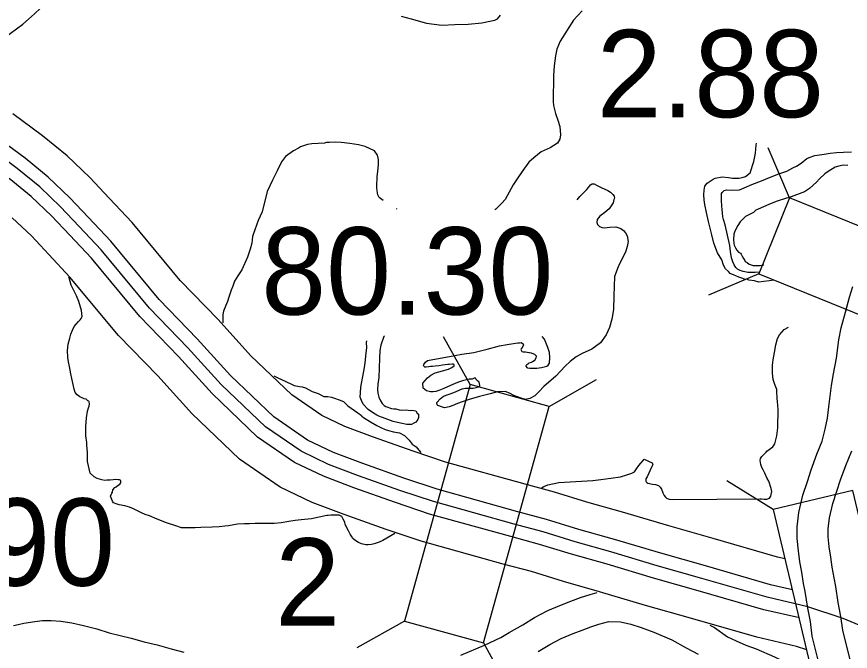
# Model space of a CAD drawing. Extents: x -83719 to 153526, y -11835 to 11446.
# Drawn here: x -2121.1 to -1986.7, y 1350 to 1452.3 of the extents above; entities that cross this region are included whole.
import ezdxf

# ---------------------------------------------------------------- set-up
doc = ezdxf.new("R2010")
doc.units = 0
for name, color, linetype in [('Level 10', 7, 'Continuous'), ('Level 19', 7, 'Continuous'), ('Level 20', 7, 'Continuous'), ('Level 23', 7, 'Continuous'), ('Level 25', 7, 'Continuous'), ('Level 58', 7, 'Continuous'), ('Level 59', 7, 'Continuous'), ('Level 9', 7, 'Continuous')]:
    doc.layers.add(name, color=color, linetype=linetype)

msp = doc.modelspace()

# ---------------------------------------------------------------- linework, layer by layer
at = {"layer": 'Level 10'}
for points in [[(-1991.5, 1347.1), (-1992.84, 1352.48), (-1993.16, 1354.81), (-1993.59, 1356.99), (-1994, 1359.64), (-1994.25, 1360.97), (-1994.55, 1362.76), (-1994.83, 1364.44), (-1995.07, 1366.21), (-1995.3, 1368.2), (-1995.29, 1370.09), (-1995.02, 1372.4), (-1994.38, 1375.18), (-1993.64, 1377.42), (-1993.01, 1379.3), (-1992.09, 1381.82), (-1991.23, 1383.88), (-1990.76, 1385.81), (-1990.41, 1387.58), (-1990.17, 1389.45), (-1989.74, 1392.87), (-1989.41, 1394.76), (-1988.94, 1397.26), (-1988.56, 1400.24), (-1988.19, 1402.19), (-1987.5, 1404.7), (-1986.83, 1407.14), (-1986.31, 1408.86)], [(-2049.5, 1349.39), (-2045.71, 1351.01), (-2043.08, 1352.24), (-2041.75, 1353.07), (-2039.54, 1354.29), (-2037.62, 1355.45), (-2035.48, 1356.58), (-2033.31, 1357.49), (-2031.76, 1358.1), (-2030.24, 1358.69), (-2028.65, 1359.19), (-2027.54, 1359.49)], [(-2121.67, 1354.19), (-2120.91, 1354.34), (-2120.01, 1354.54), (-2118.19, 1354.84), (-2116.98, 1354.96), (-2115.6, 1354.98), (-2114.02, 1354.87), (-2112.25, 1354.61), (-2110.34, 1354.18), (-2108.21, 1353.64), (-2106.25, 1352.98), (-2104.43, 1352.54), (-2102.67, 1352.11), (-2100.6, 1351.55), (-2098.5, 1351.05), (-2096.22, 1350.43), (-2094.2, 1349.89)], [(-2009.39, 1354.23), (-2008.63, 1353.83), (-2006.52, 1352.35), (-2005.1, 1351.68), (-2003.54, 1350.98), (-2001.87, 1350.44), (-1998.96, 1349.11), (-1997.59, 1348.47), (-1995.39, 1347.55), (-1994.06, 1347.05), (-1993.33, 1346.84), (-1992.24, 1346.72), (-1991.76, 1346.68)]]:
    msp.add_lwpolyline(points, dxfattribs=at)
at = {"layer": 'Level 19'}
for points in [[(-1997.23, 1364.91), (-1998.45, 1365.19), (-2008.83, 1368.18), (-2015.99, 1370.22), (-2023.46, 1372.44), (-2029.21, 1374.07), (-2034.4, 1375.67), (-2039.14, 1376.95), (-2051.99, 1380.52), (-2057.2, 1382.26), (-2063.74, 1384.58), (-2068.23, 1386.28), (-2071.94, 1388.06), (-2076.79, 1391.38), (-2083.36, 1397.66), (-2088.67, 1403.52), (-2094.77, 1409.83), (-2102.54, 1419.16), (-2106.2, 1423.1), (-2109.32, 1426.4), (-2113.02, 1429.91), (-2116.98, 1433.15), (-2121.78, 1436.68)], [(-1996.06, 1359.93), (-1999.6, 1360.76), (-2010.09, 1363.77), (-2017.27, 1365.82), (-2024.73, 1368.04), (-2030.51, 1369.68), (-2035.68, 1371.26), (-2040.35, 1372.53), (-2053.33, 1376.14), (-2058.69, 1377.93), (-2065.31, 1380.28), (-2070.03, 1382.06), (-2074.24, 1384.08), (-2079.69, 1387.81), (-2086.65, 1394.46), (-2092.01, 1400.39), (-2098.18, 1406.76), (-2105.98, 1416.13), (-2109.55, 1419.96), (-2112.57, 1423.16), (-2116.05, 1426.47), (-2119.79, 1429.53), (-2124.28, 1432.83)], [(-1994.92, 1355.39), (-2000.65, 1356.72), (-2011.24, 1359.77), (-2018.44, 1361.82), (-2025.9, 1364.04), (-2031.69, 1365.68), (-2036.83, 1367.26), (-2041.45, 1368.51), (-2054.55, 1372.15), (-2060.05, 1373.99), (-2066.75, 1376.36), (-2071.68, 1378.23), (-2076.33, 1380.47), (-2082.32, 1384.56), (-2089.64, 1391.56), (-2095.05, 1397.54), (-2101.28, 1403.98), (-2109.1, 1413.38), (-2112.58, 1417.11), (-2115.52, 1420.22), (-2118.81, 1423.34), (-2122.35, 1426.23)], [(-1993.71, 1350.23), (-1995.37, 1350.79), (-2001.81, 1352.28), (-2012.5, 1355.36), (-2019.72, 1357.42), (-2027.17, 1359.63), (-2032.99, 1361.28), (-2038.11, 1362.86), (-2042.67, 1364.09), (-2055.9, 1367.77), (-2061.54, 1369.66), (-2068.32, 1372.06), (-2073.48, 1374.01), (-2078.63, 1376.49), (-2085.22, 1380.99), (-2092.92, 1388.36), (-2098.4, 1394.41), (-2104.7, 1400.91), (-2112.55, 1410.34), (-2115.93, 1413.97), (-2118.77, 1416.98), (-2121.84, 1419.9)]]:
    msp.add_lwpolyline(points, dxfattribs=at)
at = {"layer": 'Level 20'}
for p, q in [((-1996.52, 1423.12), (-1999.95, 1431.22)), ((-2001.48, 1410.89), (-2009.58, 1407.46)), ((-2048.01, 1393.05), (-2052.33, 1400.71)), ((-2035.29, 1389.51), (-2027.63, 1393.84)), ((-1999.15, 1372.9), (-2006.65, 1377.52)), ((-2058.61, 1354.89), (-2066.27, 1350.56)), ((-2045.89, 1351.36), (-2041.56, 1343.7))]:
    msp.add_line(p, q, dxfattribs=at)
for points in [[(-2001.48, 1410.89), (-1964.78, 1396.01), (-1959.82, 1408.24), (-1996.52, 1423.12)], [(-2048.01, 1393.05), (-2058.61, 1354.89), (-2045.89, 1351.36), (-2035.29, 1389.51)], [(-1999.15, 1372.9), (-1990.01, 1334.37), (-1977.17, 1337.42), (-1986.31, 1375.95)]]:
    msp.add_lwpolyline(points, close=True, dxfattribs=at)
at = {"layer": 'Level 23'}
msp.add_arc((-2145.6, 1482.39), 40.29, 296.5429, 353.6077, dxfattribs=at)
at = {"layer": 'Level 59'}
for points in [[(-1983.1, 1353.34), (-1987.89, 1355.3), (-1993.55, 1357.21), (-2000.13, 1358.74), (-2010.66, 1361.77), (-2017.86, 1363.82), (-2025.32, 1366.04), (-2031.1, 1367.68), (-2036.25, 1369.26), (-2040.9, 1370.52), (-2053.94, 1374.15), (-2059.37, 1375.96), (-2066.03, 1378.32), (-2070.85, 1380.14), (-2075.28, 1382.27), (-2081.01, 1386.19), (-2088.14, 1393.01), (-2093.53, 1398.96), (-2099.73, 1405.37), (-2107.54, 1414.75), (-2111.07, 1418.53), (-2114.05, 1421.69), (-2117.43, 1424.9), (-2121.07, 1427.88), (-2125.42, 1431.08)], [(-1986.68, 1348.41), (-1987.92, 1353.43), (-1988.23, 1355.63), (-1988.66, 1357.86), (-1989.07, 1360.49), (-1989.33, 1361.85), (-1989.62, 1363.58), (-1989.88, 1365.18), (-1990.11, 1366.84), (-1990.3, 1368.48), (-1990.29, 1369.78), (-1990.09, 1371.55), (-1989.56, 1373.83), (-1988.89, 1375.84), (-1988.29, 1377.65), (-1987.43, 1380), (-1986.47, 1382.32)], [(-2037.04, 1349.96), (-2035.16, 1351.09), (-2033.34, 1352.06), (-2031.42, 1352.86), (-2029.94, 1353.45), (-2028.58, 1353.97), (-2027.26, 1354.39), (-2025.63, 1354.82), (-2023.77, 1354.75), (-2022.13, 1354.41), (-2020.46, 1353.87), (-2018.41, 1353.1), (-2015.5, 1351.85), (-2013.21, 1350.58), (-2011.23, 1349.55)]]:
    msp.add_lwpolyline(points, dxfattribs=at)
at = {"layer": 'Level 9'}
for points in [[(-2029.97, 1453.26), (-2031.35, 1451.8), (-2033.52, 1448.4), (-2034.03, 1447.09), (-2034.25, 1446.05), (-2034.49, 1444.44), (-2034.56, 1442.84), (-2034.63, 1438.67), (-2034.55, 1438), (-2034.23, 1436.74), (-2033.88, 1435.68), (-2033.56, 1434.61), (-2033.47, 1433.31), (-2033.56, 1432.58), (-2033.92, 1431.97), (-2035.11, 1431.22), (-2036.56, 1430.53), (-2037.77, 1429.57), (-2038.53, 1428.89), (-2039.54, 1427.54), (-2040.45, 1426.19), (-2041.1, 1425.25), (-2042.39, 1422.86), (-2042.91, 1422.25), (-2043.9, 1421.33), (-2044.03, 1421.22)], [(-2059.12, 1452.45), (-2057.55, 1452.01), (-2055.08, 1451.32), (-2052.57, 1450.96), (-2050.48, 1451.06), (-2048.35, 1451.16), (-2046.12, 1451.33), (-2044.83, 1451.62), (-2044.03, 1451.8), (-2043.6, 1452), (-2043.14, 1452.58)], [(-2062.04, 1422.71), (-2062.67, 1423.19), (-2062.91, 1423.62), (-2062.99, 1424.26), (-2063.06, 1424.79), (-2063.08, 1425.52), (-2063.02, 1426.06), (-2062.99, 1426.53), (-2062.91, 1427.43), (-2062.79, 1428.43), (-2062.77, 1429.33), (-2062.95, 1430.03), (-2063.46, 1430.69), (-2064.97, 1431.4), (-2066.01, 1431.68), (-2067.44, 1431.89), (-2068.81, 1432.04), (-2069.71, 1432.09), (-2070.67, 1432.07), (-2071.17, 1432.03), (-2071.5, 1431.96), (-2073.57, 1431.86), (-2074.23, 1431.71), (-2075.39, 1431.33), (-2075.72, 1431.16), (-2076.48, 1430.71), (-2077.79, 1429.79), (-2078.44, 1428.94), (-2079.12, 1427.5), (-2079.89, 1425.98), (-2080.73, 1424.17), (-2081.57, 1420.85), (-2082.19, 1419.5), (-2082.73, 1417.96), (-2083.11, 1416.89), (-2083.22, 1415.82), (-2083.47, 1414.88), (-2083.92, 1413.54), (-2084.85, 1411.52), (-2085.5, 1410.54), (-2085.99, 1409.7), (-2086.31, 1408.89), (-2086.53, 1408.25), (-2086.91, 1407.11), (-2087.16, 1406.41), (-2087.48, 1405.64), (-2087.8, 1404.86), (-2087.9, 1404.33), (-2087.92, 1404.03), (-2087.91, 1403.33), (-2087.87, 1402.98)], [(-2009.04, 1417.16), (-2009.58, 1419.32), (-2009.9, 1420.75), (-2010.19, 1422.08), (-2010.27, 1422.81), (-2010.31, 1423.61), (-2010.29, 1424.38), (-2010.2, 1425.02), (-2009.78, 1425.52), (-2009.32, 1425.83), (-2008.82, 1426.17), (-2008.53, 1426.28), (-2007.4, 1426.5), (-2006.36, 1426.41), (-2005.73, 1426.32), (-2005.13, 1426.3), (-2004.66, 1426.31), (-2004.17, 1426.42), (-2003.64, 1426.56), (-2002.85, 1427.17), (-2002.28, 1428.98), (-2002.03, 1430.36), (-2001.89, 1431.63), (-2001.83, 1431.94)], [(-2006.66, 1424.41), (-2005.73, 1424.35), (-2004.57, 1424.41), (-2003.81, 1424.72), (-2002.58, 1425.31), (-2001.06, 1425.9), (-1999.74, 1426.39), (-1998.25, 1427.01), (-1996.96, 1427.43), (-1996, 1427.95), (-1995.37, 1428.26), (-1994.65, 1428.71), (-1993.7, 1429.49), (-1993.33, 1429.66), (-1992.44, 1429.98), (-1990.95, 1430.17), (-1989.95, 1430.32), (-1988.95, 1430.43), (-1987.79, 1430.52), (-1986.52, 1430.57)], [(-1987.12, 1428.35), (-1987.89, 1428.42), (-1988.58, 1428.24), (-1989.15, 1428.06), (-1990.27, 1427.38), (-1990.83, 1427), (-1991.68, 1426.19), (-1992.17, 1425.64), (-1993.29, 1424.66), (-1994.11, 1424.11), (-1996.26, 1423.31), (-1997.15, 1423.03), (-1998.51, 1422.57), (-1999.74, 1422.12), (-2000.36, 1421.87), (-2001.95, 1421.15), (-2002.34, 1420.77), (-2003.63, 1420.12), (-2003.96, 1419.78), (-2004.45, 1419.27), (-2004.84, 1418.66), (-2005.36, 1417.75), (-2005.48, 1417.28), (-2005.53, 1416.38), (-2005.52, 1415.82), (-2005.45, 1415.52), (-2005.25, 1415.05), (-2005.04, 1414.72), (-2004.77, 1414.36), (-2004.53, 1414.26), (-2004.43, 1414.2), (-2004.3, 1414.03), (-2004.16, 1413.74), (-2003.95, 1413.37), (-2003.71, 1413.01), (-2003.65, 1412.88), (-2003.34, 1412.68), (-2003.04, 1412.42), (-2002.84, 1412.36), (-2002.37, 1412.2), (-2001.67, 1412.21), (-2001.24, 1412.21), (-2000.65, 1412.34)], [(-2030.75, 1422.81), (-2030.32, 1423.35), (-2029.53, 1424.13), (-2029.2, 1424.47), (-2028.94, 1424.81), (-2028.62, 1425.25), (-2028.35, 1425.39), (-2028.02, 1425.39), (-2027.65, 1425.2), (-2026.88, 1424.81), (-2025.84, 1424.29), (-2025.4, 1424.03), (-2024.99, 1423.67), (-2024.79, 1423.38), (-2024.75, 1423.08), (-2024.85, 1422.84), (-2024.97, 1422.34), (-2025.62, 1421.36), (-2026.31, 1420.78), (-2027.1, 1420.17), (-2027.56, 1419.63), (-2027.58, 1419.13), (-2027.48, 1418.86), (-2027.17, 1418.53), (-2026.74, 1418.37), (-2026.37, 1418.31), (-2025.47, 1418.43), (-2024.54, 1418.44), (-2023.74, 1418.19), (-2023.3, 1417.86), (-2022.96, 1417.47), (-2022.72, 1417), (-2022.51, 1416.07), (-2022.69, 1415.27), (-2022.98, 1414.36), (-2023.59, 1413.15), (-2024.17, 1412.01), (-2024.74, 1410.43), (-2024.82, 1408.86), (-2024.86, 1407.32), (-2024.89, 1405.15), (-2025.16, 1403.55), (-2025.54, 1402.24), (-2026.09, 1401.03), (-2027, 1399.78), (-2028.41, 1398.72), (-2029.93, 1398.06), (-2030.92, 1397.48), (-2031.88, 1396.73), (-2032.7, 1395.98), (-2034.2, 1394.39), (-2036.14, 1392.72), (-2036.92, 1391.84), (-2037.58, 1391.23), (-2038.37, 1390.79), (-2039.07, 1390.61), (-2039.8, 1390.83), (-2040.98, 1391.28), (-2041.65, 1391.63), (-2042.35, 1391.89), (-2043.62, 1391.87), (-2044.77, 1391.52), (-2046.53, 1391.09), (-2048.16, 1390.59), (-2049.45, 1390.17), (-2050.31, 1389.86), (-2050.67, 1389.72), (-2051.4, 1389.41), (-2052.16, 1389.29), (-2052.66, 1389.45), (-2053.07, 1389.61), (-2053.23, 1389.64), (-2053.33, 1389.74), (-2053.41, 1390.14), (-2052.85, 1390.72), (-2052.29, 1391.13), (-2050.67, 1391.72), (-2049.28, 1392.31), (-2048.75, 1392.42), (-2048.12, 1392.43), (-2047.52, 1392.44), (-2047.06, 1392.55)], [(-2001.33, 1411.14), (-2002.05, 1411.1), (-2002.68, 1411.09), (-2003.22, 1411.11), (-2003.48, 1411.14), (-2003.99, 1411.27), (-2004.45, 1411.43), (-2004.89, 1411.62), (-2005.19, 1411.88), (-2005.47, 1412.31), (-2005.64, 1412.81), (-2005.89, 1413.47), (-2006.03, 1414.47), (-2006.15, 1415.44), (-2006.87, 1418.8), (-2007.15, 1419.63), (-2007.26, 1420.09), (-2007.3, 1420.69), (-2007.38, 1421.22), (-2007.42, 1421.82), (-2007.47, 1422.72), (-2007.48, 1423.23), (-2007.51, 1423.46), (-2007.49, 1423.83), (-2007.39, 1423.99), (-2007.29, 1424.1), (-2007.06, 1424.3), (-2006.66, 1424.41)], [(-2059.81, 1421.3), (-2059.91, 1421.36)], [(-1999.05, 1409.87), (-1999.73, 1409.77), (-2000.66, 1409.62), (-2001.49, 1409.54), (-2002.16, 1409.76), (-2003.06, 1409.88), (-2003.3, 1409.94), (-2003.8, 1410.04), (-2004.2, 1410.16), (-2004.7, 1410.36), (-2005.17, 1410.55), (-2005.44, 1410.64), (-2006.08, 1410.93), (-2006.38, 1411.23), (-2006.82, 1411.66), (-2007.16, 1412.28), (-2007.44, 1413.11), (-2008.13, 1414.27), (-2008.72, 1415.8), (-2009.04, 1417.16)], [(-2073.61, 1371.39), (-2075.24, 1371.23), (-2076.23, 1371.11), (-2077.26, 1370.93), (-2078.49, 1370.71), (-2079.62, 1370.62), (-2081.38, 1370.6), (-2082.68, 1370.61), (-2083.61, 1370.59), (-2084.38, 1370.58), (-2085.54, 1370.49), (-2086.97, 1370.24), (-2087.57, 1370.19), (-2088.5, 1370.11), (-2089.63, 1370.03), (-2091.43, 1370), (-2092.36, 1369.92), (-2093.56, 1369.9), (-2094.56, 1369.95), (-2095.46, 1370.27), (-2097, 1370.71), (-2098.51, 1371.32), (-2099.71, 1371.87), (-2100.42, 1372.05), (-2101.02, 1372.34), (-2102.3, 1372.99), (-2102.93, 1373.28), (-2103.7, 1373.47), (-2104.6, 1373.65), (-2104.94, 1373.75), (-2105.51, 1373.97), (-2105.71, 1374.2), (-2105.99, 1375.03), (-2105.8, 1375.54), (-2105.7, 1375.67), (-2105.61, 1376.04), (-2105.32, 1376.41), (-2105.08, 1376.55), (-2104.79, 1376.79), (-2104.49, 1376.99), (-2104.36, 1377.16), (-2104.36, 1377.33), (-2104.33, 1377.53), (-2104.57, 1377.66), (-2104.8, 1377.69), (-2105.17, 1377.72), (-2105.6, 1377.68), (-2106.07, 1377.6), (-2106.6, 1377.59), (-2106.93, 1377.55), (-2107.4, 1377.65), (-2108.17, 1377.87), (-2108.67, 1378.16), (-2109.28, 1378.72), (-2109.71, 1380.61), (-2109.72, 1381.28), (-2109.74, 1382.05), (-2109.85, 1383.25), (-2109.83, 1383.71), (-2109.98, 1384.78), (-2109.97, 1386.28), (-2109.92, 1386.95), (-2109.86, 1387.68), (-2109.71, 1388.72), (-2109.55, 1389.29), (-2109.46, 1389.53), (-2109.4, 1389.93), (-2109.44, 1390.23), (-2109.5, 1390.33), (-2109.64, 1390.42), (-2109.91, 1390.65), (-2110.24, 1390.72), (-2110.48, 1390.81), (-2110.95, 1391.07), (-2111.39, 1391.36), (-2111.69, 1391.73), (-2111.87, 1392.26), (-2112.01, 1393.02), (-2112.23, 1393.99), (-2112.41, 1394.78), (-2112.63, 1395.95), (-2112.77, 1396.68), (-2112.88, 1397.41), (-2112.97, 1398.51), (-2112.85, 1399.52), (-2112.57, 1400.52), (-2112.41, 1401.16), (-2112.16, 1401.8), (-2111.87, 1402.37), (-2111.54, 1402.77), (-2111.15, 1403.18), (-2110.88, 1403.45), (-2110.72, 1403.69), (-2110.59, 1404.02), (-2110.68, 1404.99), (-2111.1, 1406.42), (-2111.48, 1407.31), (-2112.37, 1409.07), (-2112.69, 1410.23), (-2112.71, 1410.32)], [(-2036.54, 1376.34), (-2036.14, 1376.57), (-2035.48, 1376.88), (-2033.72, 1377.21), (-2028.23, 1377.54), (-2026.97, 1377.72), (-2025.34, 1377.92), (-2023.78, 1378.14), (-2022.76, 1378.49), (-2021.96, 1378.74), (-2021.53, 1378.98), (-2021.17, 1379.42), (-2020.82, 1379.96), (-2020.49, 1380.36), (-2020.13, 1380.8), (-2019.97, 1380.97), (-2018.66, 1380.39), (-2018.56, 1380.16), (-2018.72, 1379.79), (-2019.49, 1378.15), (-2019.68, 1377.84), (-2019.71, 1377.47), (-2019.64, 1377.34), (-2019.51, 1377.24), (-2019.34, 1377.15), (-2018.6, 1376.99), (-2018.14, 1376.9), (-2017.67, 1376.74), (-2017.36, 1376.48), (-2017.16, 1376.15), (-2016.95, 1375.58), (-2016.74, 1375.15), (-2016.54, 1374.89), (-2016.34, 1374.69), (-2015.9, 1374.53), (-2015.17, 1374.51), (-2001.29, 1374.6), (-2001.02, 1374.58), (-2000.62, 1374.52), (-2000.19, 1374.52), (-1999.76, 1374.7), (-1999.53, 1375.03), (-1999.47, 1375.3), (-1999.38, 1375.77), (-1999.48, 1376.27), (-1999.87, 1377.46), (-2000.11, 1377.89), (-2000.52, 1378.72), (-2000.76, 1379.28), (-2000.97, 1379.65), (-2001.14, 1380.11), (-2001.26, 1380.78), (-2001.19, 1381.08), (-2000.97, 1381.45), (-2000.64, 1381.76), (-2000.28, 1382.13), (-2000.15, 1382.26), (-1999.19, 1383.01), (-1998.9, 1383.45), (-1998.56, 1384.76), (-1998.38, 1386.03), (-1998.36, 1389), (-1998.48, 1390.3), (-1998.49, 1390.8), (-1998.54, 1391.97), (-1998.58, 1392.23), (-1998.86, 1393.03), (-1999.03, 1393.5), (-1999.14, 1393.86), (-1999.26, 1394.86), (-1999.24, 1396.13), (-1999.16, 1397), (-1998.94, 1398.2), (-1998.7, 1399.44), (-1998.45, 1400.45), (-1998.16, 1401.05), (-1997.37, 1401.9), (-1996.7, 1402.29)], [(-2061.85, 1400.9), (-2061.94, 1400.75), (-2062.41, 1399.4), (-2062.6, 1398.5), (-2062.61, 1397.26), (-2062.69, 1395.66), (-2062.76, 1394.16), (-2062.88, 1393.09), (-2062.96, 1392.25), (-2062.92, 1391.65), (-2062.74, 1390.99), (-2062.5, 1390.49), (-2062.23, 1389.96), (-2061.89, 1389.63), (-2061.62, 1389.51), (-2060.68, 1389.19), (-2060.32, 1389.13), (-2060.02, 1389.13), (-2059.48, 1388.97), (-2059.05, 1388.88), (-2058.31, 1388.93), (-2057.71, 1388.83), (-2057.42, 1388.87), (-2057.11, 1388.84), (-2056.78, 1388.78), (-2056.54, 1388.42), (-2056.37, 1388.26), (-2056.33, 1387.96), (-2056.33, 1387.72), (-2056.43, 1387.39), (-2056.78, 1386.98), (-2057.11, 1386.78), (-2057.48, 1386.57), (-2058.21, 1386.59), (-2059.25, 1386.81), (-2060.42, 1387.09), (-2061.72, 1387.57), (-2062.73, 1387.92), (-2063.09, 1388.08), (-2063.77, 1388.54), (-2064.48, 1389.03), (-2065.29, 1389.85), (-2065.56, 1390.48), (-2065.74, 1391.01)], [(-2047.06, 1392.55), (-2046.66, 1392.65), (-2046.53, 1392.72), (-2046.43, 1392.86), (-2046.57, 1393.39), (-2046.81, 1393.65), (-2047.08, 1393.88), (-2047.18, 1394.05), (-2047.38, 1394.08), (-2047.71, 1393.9), (-2048.18, 1393.9), (-2049.27, 1393.61), (-2050.06, 1393.36), (-2051.19, 1392.88), (-2052.28, 1392.39), (-2053.04, 1392.05), (-2053.54, 1391.91), (-2054, 1391.83), (-2054.43, 1391.83), (-2055.07, 1392.01), (-2055.61, 1392.47), (-2055.66, 1393.24), (-2054.9, 1394.12), (-2054.35, 1394.56), (-2053.65, 1394.94), (-2052.46, 1395.23), (-2051.5, 1395.51), (-2050.97, 1395.75), (-2050.58, 1396.06), (-2050.61, 1396.19), (-2050.75, 1396.32), (-2050.91, 1396.29), (-2051.38, 1396.28), (-2051.64, 1396.24), (-2052.47, 1396.13), (-2053.04, 1396.05), (-2053.67, 1395.98), (-2054.07, 1395.94), (-2054.4, 1395.93), (-2054.7, 1395.86), (-2055.1, 1395.82), (-2055.3, 1395.85), (-2055.37, 1395.88), (-2055.47, 1395.98), (-2055.54, 1396.11), (-2055.51, 1396.25), (-2055.24, 1396.62), (-2054.92, 1396.89), (-2050.5, 1397.73), (-2049.37, 1397.95), (-2047.41, 1398.21), (-2045.29, 1398.75), (-2043.3, 1399.28), (-2042.04, 1399.47), (-2041.05, 1399.65), (-2040.68, 1399.72), (-2040.32, 1399.73), (-2040.28, 1399.73), (-2040.05, 1399.77), (-2039.78, 1399.81), (-2039.72, 1399.77), (-2039.48, 1399.58), (-2039.44, 1399.38), (-2039.64, 1399.01), (-2039.8, 1398.8), (-2039.87, 1398.7), (-2039.76, 1398.47), (-2039.66, 1398.34), (-2039.46, 1398.28), (-2039.09, 1398.28), (-2038.56, 1398.19), (-2038.46, 1398.19), (-2038.19, 1398.16), (-2037.82, 1398), (-2037.66, 1397.91), (-2037.39, 1397.68), (-2037.38, 1397.54), (-2037.45, 1397.31), (-2037.54, 1397.04), (-2037.67, 1396.87), (-2037.94, 1396.7), (-2038.2, 1396.59), (-2038.53, 1396.46), (-2038.73, 1396.32), (-2038.89, 1396.22), (-2039.02, 1396.05), (-2039.02, 1395.98), (-2038.85, 1395.78), (-2038.75, 1395.72), (-2038.38, 1395.66), (-2037.25, 1395.68), (-2036.52, 1395.75), (-2036.06, 1395.9), (-2035.66, 1395.97), (-2035.43, 1396.17), (-2035.24, 1396.48), (-2035.15, 1397.38), (-2035.2, 1398.21), (-2035.48, 1399.01), (-2036.03, 1400.33), (-2036.4, 1400.77)], [(-2065.74, 1391.01), (-2065.72, 1391.67), (-2065.63, 1392.58), (-2065.51, 1393.21), (-2065.39, 1394.05), (-2065.14, 1395.19), (-2064.99, 1396.09), (-2064.87, 1397.03), (-2064.76, 1398.16), (-2064.7, 1398.97), (-2064.72, 1399.8), (-2064.68, 1400.1)], [(-2079.67, 1394.43), (-2079.01, 1394.13), (-2077.87, 1393.55), (-2076.59, 1393), (-2076.39, 1392.87)], [(-2076.39, 1392.87), (-2075.52, 1392.72), (-2075.12, 1392.66), (-2074.55, 1392.5), (-2073.51, 1391.91), (-2072.51, 1391.6), (-2071.63, 1391.11), (-2070.97, 1391.09), (-2070.4, 1391), (-2070.06, 1390.87), (-2069.13, 1390.55), (-2068.42, 1390.3), (-2067.75, 1389.61), (-2066.13, 1388.46), (-2065.56, 1388.04), (-2065.46, 1387.94), (-2065.22, 1387.74), (-2064.08, 1387.03), (-2063.07, 1386.45), (-2062.43, 1386.12), (-2061.73, 1385.8), (-2061.19, 1385.64), (-2060.35, 1385.42), (-2059.75, 1385.3), (-2059.42, 1385.24), (-2058.58, 1384.82), (-2057.87, 1384.06), (-2057.36, 1383.4), (-2056.72, 1382.98), (-2056.31, 1382.45), (-2055.96, 1382.08)], [(-2060.18, 1369.03), (-2061.44, 1368.25), (-2062.1, 1367.87), (-2062.69, 1367.63), (-2063.49, 1367.35), (-2063.95, 1367.21), (-2064.48, 1367.17), (-2064.85, 1367.16), (-2065.52, 1367.32), (-2066.02, 1367.58), (-2066.59, 1367.93), (-2066.93, 1368.23), (-2067.17, 1368.59), (-2067.37, 1368.89), (-2067.65, 1369.45), (-2068.1, 1370.34), (-2068.17, 1370.51), (-2068.21, 1370.84), (-2068.51, 1371.34), (-2068.69, 1371.77), (-2068.72, 1371.77), (-2069.12, 1371.96), (-2069.32, 1371.96), (-2069.82, 1371.95), (-2070.29, 1371.94), (-2070.49, 1371.94), (-2070.92, 1371.93), (-2071.15, 1371.93), (-2073.61, 1371.39)]]:
    msp.add_lwpolyline(points, dxfattribs=at)

# ---------------------------------------------------------------- texts
at = {"layer": 'Level 20'}
msp.add_text('2', height=14.08, dxfattribs=at).set_placement((-2079.46, 1354.15))
at = {"layer": 'Level 25'}
msp.add_text('1.90', height=14.08, dxfattribs=at).set_placement((-2141.92, 1360.59))
at = {"layer": 'Level 58'}
for s, p in [('2.88', (-2027.6, 1436.13)), ('80.30', (-2081.71, 1404.31))]:
    msp.add_text(s, height=14.08, dxfattribs=at).set_placement(p)

doc.saveas('drawing.dxf')
